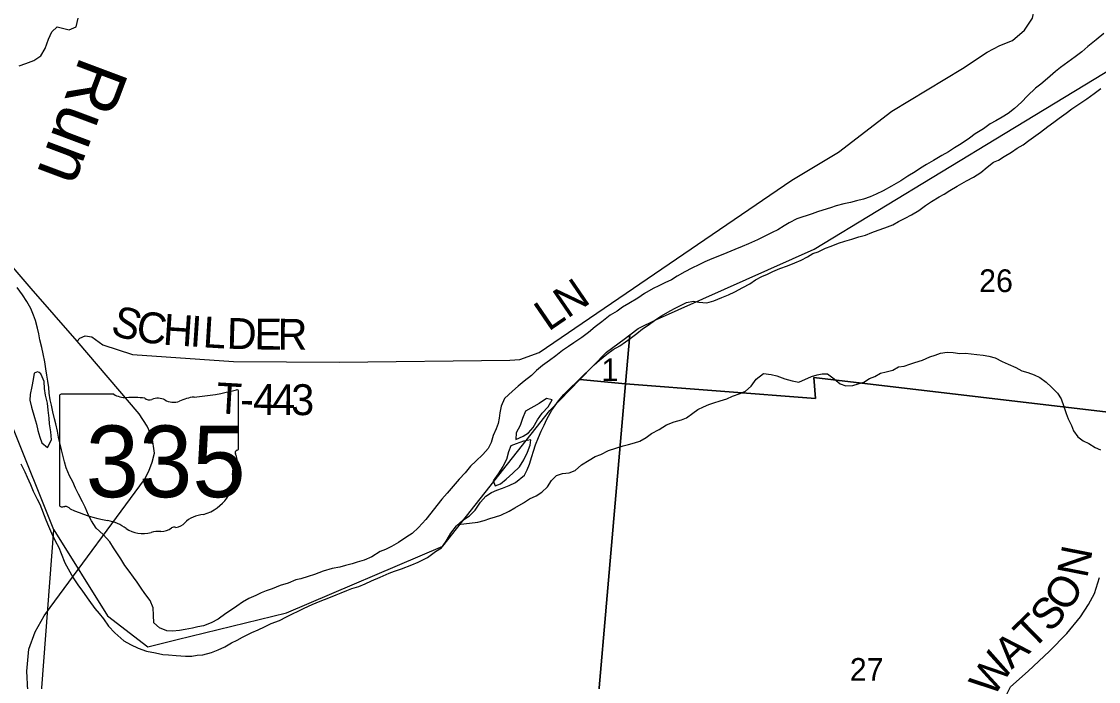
# Model space of a CAD drawing. Extents: x 5.6 to 39.6, y 0.7 to 22.7.
# Drawn here: x 9.058 to 11.039, y 15.732 to 16.946 of the extents above; entities that cross this region are included whole.
import ezdxf

# ---------------------------------------------------------------- set-up
doc = ezdxf.new("R2010")
doc.units = 0
doc.layers.add('Default', color=7, linetype='Continuous')

msp = doc.modelspace()

# ---------------------------------------------------------------- linework, layer by layer
at = {"layer": 'Default'}
for p, q in [((9.4573, 16.161), (9.4573, 16.2657)), ((9.1277, 16.2573), (9.1277, 16.0571)), ((9.2275, 16.2607), (9.1309, 16.2607)), ((9.4572, 16.161), (9.4573, 16.161))]:
    msp.add_line(p, q, dxfattribs=at)
for points in [[(9.1605, 16.3581), (9.1651, 16.3637), (9.1749, 16.3682), (9.1874, 16.3659), (9.2074, 16.3517), (9.2618, 16.3336), (9.4481, 16.3211), (9.6428, 16.3196), (9.956, 16.3235), (9.9746, 16.3245), (10.0103, 16.3372), (10.475, 16.6545), (10.5609, 16.706), (10.6587, 16.7813), (10.7891, 16.8599), (10.8343, 16.8896), (10.8575, 16.9024), (10.8806, 16.9114), (10.9027, 16.9302), (10.9176, 16.9521), (10.9207, 16.9673), (10.9185, 16.9795)], [(9.0533, 16.8646), (9.0659, 16.8691), (9.0807, 16.8746), (9.0933, 16.8828), (9.1014, 16.8964), (9.1077, 16.9137), (9.1139, 16.9273), (9.1235, 16.9363), (9.1356, 16.9335), (9.1458, 16.9311), (9.1587, 16.9367), (9.1623, 16.9526)], [(11.0491, 16.9244), (11.035, 16.9124), (11.0197, 16.9004), (11.0082, 16.8907), (10.996, 16.881), (10.9693, 16.8615), (10.9598, 16.854), (10.9452, 16.8417), (10.933, 16.8312), (10.9231, 16.8237), (10.9086, 16.8098), (10.8971, 16.7978), (10.8848, 16.7862), (10.8726, 16.7772), (10.8616, 16.7705), (10.8501, 16.7637), (10.8399, 16.7578), (10.8273, 16.7488), (10.8124, 16.7395), (10.8017, 16.7316), (10.7865, 16.7215), (10.7743, 16.7141), (10.7632, 16.7066), (10.7506, 16.6999), (10.7354, 16.6906), (10.7224, 16.6831), (10.7114, 16.6764), (10.7015, 16.6697), (10.6885, 16.6619), (10.6756, 16.6533), (10.6584, 16.6436), (10.6432, 16.6346), (10.6302, 16.6287), (10.6188, 16.6239), (10.6067, 16.6195), (10.5938, 16.6162), (10.5827, 16.6136), (10.5706, 16.6111), (10.5562, 16.6071), (10.5459, 16.6038), (10.5318, 16.5994), (10.522, 16.596), (10.5125, 16.5923)], [(10.5036, 16.5132), (10.5136, 16.5192), (10.5235, 16.5225), (10.5368, 16.5292), (10.5471, 16.5332), (10.5608, 16.5384), (10.5726, 16.5421), (10.5855, 16.5458), (10.598, 16.5502), (10.6102, 16.5535), (10.6223, 16.5583), (10.6337, 16.5623), (10.6459, 16.5664), (10.6607, 16.5723), (10.6714, 16.5786), (10.6836, 16.5846), (10.695, 16.5905), (10.7083, 16.5987), (10.7209, 16.6077), (10.732, 16.6152), (10.7457, 16.6238), (10.7552, 16.6286), (10.7655, 16.6353), (10.7789, 16.6435), (10.7964, 16.6532), (10.809, 16.6599), (10.8223, 16.6685), (10.8345, 16.6786), (10.8456, 16.6872), (10.8551, 16.6913), (10.8654, 16.698), (10.8787, 16.7058), (10.8894, 16.7133), (10.9005, 16.7193), (10.9111, 16.7275), (10.9325, 16.7425), (10.9459, 16.7533), (10.9566, 16.7608), (10.9669, 16.7687), (10.9795, 16.7776), (10.9901, 16.7855), (11.0046, 16.7956), (11.0176, 16.8038), (11.0313, 16.8139), (11.0432, 16.8232)], [(10.5125, 16.5923), (10.4843, 16.5835), (10.4702, 16.5757), (10.4607, 16.5702), (10.4489, 16.5631), (10.4386, 16.5579), (10.412, 16.5449), (10.3952, 16.5371), (10.3835, 16.5323), (10.3698, 16.5268), (10.3554, 16.5209), (10.3447, 16.5165), (10.328, 16.5095), (10.3147, 16.5039), (10.304, 16.4984), (10.2907, 16.4924), (10.2782, 16.4858), (10.2637, 16.478), (10.2534, 16.4712), (10.2413, 16.4653), (10.2303, 16.4598), (10.2196, 16.4549), (10.204, 16.446), (10.1914, 16.4374), (10.1751, 16.4274), (10.1636, 16.4207), (10.1533, 16.4136), (10.1408, 16.4058), (10.1251, 16.3938), (10.1133, 16.3845), (10.1007, 16.3744), (10.0885, 16.365), (10.074, 16.3554), (10.0638, 16.3483), (10.0531, 16.3408), (10.0405, 16.3315), (10.0294, 16.3229), (10.0165, 16.3132), (10.0054, 16.3042), (9.9959, 16.2952), (9.9825, 16.2847), (9.9714, 16.2757), (9.9611, 16.2664), (9.9466, 16.2529), (9.94, 16.2389), (9.938, 16.2265), (9.9368, 16.2166), (9.9344, 16.2068), (9.9313, 16.197), (9.9258, 16.1849), (9.9219, 16.172), (9.9161, 16.1611), (9.9065, 16.1498), (9.8936, 16.1375), (9.8836, 16.1281), (9.8737, 16.1161), (9.8629, 16.1041), (9.8522, 16.0917), (9.8411, 16.0789), (9.8311, 16.0673), (9.8216, 16.056), (9.8108, 16.0421), (9.8016, 16.0305), (9.7882, 16.0154), (9.7764, 16.0046), (9.7669, 15.9986), (9.7512, 15.9878), (9.7383, 15.9804), (9.7276, 15.9752), (9.7178, 15.9715), (9.7025, 15.9618), (9.6881, 15.9555), (9.6756, 15.9515), (9.6661, 15.9486), (9.654, 15.9457), (9.6433, 15.9428), (9.6293, 15.9399), (9.6126, 15.9351), (9.5967, 15.9289), (9.5849, 15.9256), (9.572, 15.9212), (9.5625, 15.919), (9.5484, 15.9131), (9.5336, 15.9087), (9.5192, 15.9024), (9.5082, 15.8988), (9.4987, 15.8951), (9.4892, 15.8907), (9.4763, 15.8851), (9.4641, 15.8784), (9.4538, 15.871), (9.4439, 15.8642), (9.434, 15.8571), (9.4199, 15.8467), (9.407, 15.84), (9.3925, 15.8349), (9.3823, 15.8327), (9.3724, 15.8305), (9.3592, 15.828), (9.3486, 15.8263), (9.3357, 15.8249)], [(9.0759, 16.4554), (9.0097, 16.5316)], [(9.328, 15.781), (9.3424, 15.7801), (9.3598, 15.7787), (9.3715, 15.7786), (9.3813, 15.7804), (9.3912, 15.7814), (9.4071, 15.7854), (9.4197, 15.7902), (9.4318, 15.7961), (9.4444, 15.8032), (9.4543, 15.8084), (9.4645, 15.814), (9.4817, 15.8225), (9.4931, 15.8273), (9.5048, 15.8328), (9.517, 15.8388), (9.5326, 15.8443), (9.5451, 15.851), (9.5778, 15.8669), (9.5927, 15.8739), (9.6075, 15.8798), (9.6231, 15.8861), (9.6364, 15.8917), (9.6462, 15.895), (9.6561, 15.8994), (9.6656, 15.9031), (9.6781, 15.9067), (9.6899, 15.9119), (9.7017, 15.9171), (9.7176, 15.9241), (9.734, 15.9315), (9.7439, 15.9352), (9.7568, 15.9396), (9.7758, 15.9466), (9.7875, 15.9518), (9.805, 15.9603), (9.8195, 15.9711), (9.8302, 15.9782), (9.839, 15.9906), (9.8479, 16.0049), (9.8582, 16.0184), (9.8697, 16.0289), (9.8819, 16.0368), (9.8922, 16.0476), (9.9022, 16.0623), (9.9122, 16.0732), (9.9224, 16.0799), (9.9323, 16.0843), (9.9426, 16.088), (9.9551, 16.0928), (9.9665, 16.098), (9.9829, 16.1115), (9.9879, 16.1213), (9.9922, 16.1318), (9.9969, 16.1462), (9.9997, 16.156), (10.0032, 16.1673), (10.009, 16.1809), (10.0141, 16.1926), (10.0191, 16.2039), (10.0241, 16.2149), (10.0334, 16.2311), (10.0457, 16.2484), (10.0553, 16.2604), (10.0671, 16.2716), (10.0793, 16.2833), (10.0919, 16.2956), (10.1019, 16.3058), (10.1114, 16.3144), (10.1214, 16.3234), (10.1343, 16.3342), (10.1465, 16.3428), (10.1583, 16.3499), (10.169, 16.3573), (10.1801, 16.3652), (10.1896, 16.3726), (10.2003, 16.3812), (10.2109, 16.3879), (10.2247, 16.398), (10.2353, 16.4051), (10.2509, 16.414), (10.2605, 16.4192), (10.281, 16.4292), (10.2939, 16.4317), (10.3041, 16.4301), (10.3184, 16.4288), (10.3317, 16.4325), (10.3462, 16.4387), (10.3583, 16.4435), (10.3701, 16.4491), (10.3846, 16.4569), (10.3975, 16.4639), (10.4078, 16.471), (10.4196, 16.4773), (10.4302, 16.4814), (10.4397, 16.4866), (10.453, 16.4921), (10.4667, 16.4969), (10.4807, 16.5021), (10.4918, 16.5072), (10.5036, 16.5132)], [(9.3357, 15.8249), (9.3255, 15.8254), (9.3119, 15.8308), (9.3014, 15.8404), (9.3008, 15.8545), (9.2998, 15.8678), (9.2943, 15.8815), (9.285, 15.8941), (9.2783, 15.9036), (9.2708, 15.9147), (9.2637, 15.9243), (9.2559, 15.9354), (9.2477, 15.9453), (9.2406, 15.9579), (9.2332, 15.9686), (9.2272, 15.9781), (9.2202, 15.9892), (9.2078, 16.0026), (9.1955, 16.0145), (9.1865, 16.0279), (9.181, 16.0382), (9.1747, 16.0527), (9.1703, 16.0626), (9.1629, 16.0767), (9.1569, 16.0881), (9.1525, 16.0992), (9.1462, 16.1106), (9.1399, 16.1251), (9.137, 16.1365), (9.1341, 16.1487), (9.1312, 16.1582), (9.1283, 16.1711), (9.1258, 16.1814), (9.124, 16.1924), (9.1211, 16.2061), (9.1186, 16.2156), (9.1157, 16.2281), (9.1128, 16.2403), (9.1106, 16.2502), (9.1089, 16.2623), (9.1079, 16.2733), (9.1065, 16.2847), (9.1047, 16.2957), (9.1025, 16.3071), (9.1008, 16.3204), (9.0979, 16.3348), (9.095, 16.3466), (9.0918, 16.3607), (9.0896, 16.3717), (9.0871, 16.382), (9.0835, 16.3964), (9.0801, 16.4059), (9.075, 16.4185), (9.0676, 16.4311), (9.0597, 16.4433), (9.0501, 16.4567)], [(9.071, 15.7062), (9.0694, 15.7157), (9.0678, 15.751), (9.0715, 15.7916), (9.0832, 15.8235), (9.0994, 15.8528), (9.1107, 15.8684), (9.2839, 16.1036), (9.2922, 16.1192), (9.2982, 16.1355), (9.3024, 16.1522), (9.2985, 16.1818), (9.2893, 16.2016), (9.2741, 16.2247), (9.1605, 16.3581), (9.0759, 16.4554)], [(8.2518, 15.7856), (8.2639, 15.7623), (8.2659, 15.4721), (9.0725, 15.4217), (9.1174, 16.0112), (9.0418, 16.1995), (9.0049, 16.4106), (8.3039, 16.4383), (8.2518, 16.391)], [(10.5109, 16.2932), (10.5212, 16.2964), (10.5308, 16.2984), (10.5406, 16.2982), (10.5525, 16.2892), (10.5637, 16.2795), (10.5742, 16.2759), (10.5871, 16.2767), (10.597, 16.2799), (10.6073, 16.2827), (10.618, 16.2893), (10.6276, 16.2932), (10.6383, 16.2991), (10.6486, 16.3019), (10.6604, 16.305), (10.6712, 16.3109), (10.6814, 16.3122), (10.6917, 16.3157), (10.7013, 16.3189), (10.7154, 16.3232), (10.7288, 16.3293), (10.7387, 16.3325), (10.7482, 16.3361), (10.7604, 16.3377), (10.7717, 16.3371), (10.7842, 16.3353), (10.7941, 16.3362), (10.8152, 16.3335), (10.8269, 16.3324), (10.8375, 16.3307), (10.8492, 16.3274), (10.8619, 16.321), (10.8731, 16.3162), (10.887, 16.3095), (10.8982, 16.3035), (10.9092, 16.3006), (10.9208, 16.2962), (10.9313, 16.2914), (10.9425, 16.2828), (10.9525, 16.2739), (10.9636, 16.2623), (10.9702, 16.2519), (10.9755, 16.2381), (10.9798, 16.2251), (10.9834, 16.2152), (10.9892, 16.2033), (10.9931, 16.193), (11.0008, 16.1822), (11.0109, 16.1747), (11.021, 16.17), (11.0329, 16.1629), (11.0427, 16.1585)], [(9.081, 16.2996), (9.0793, 16.2879), (9.0769, 16.2746), (9.0741, 16.2602), (9.0732, 16.25), (9.0761, 16.2367), (9.0819, 16.2176), (9.0852, 16.2058), (9.0881, 16.194), (9.0914, 16.1815), (9.0954, 16.1712), (9.1056, 16.1627), (9.1133, 16.177), (9.1116, 16.1915), (9.1095, 16.2063), (9.1085, 16.2169), (9.1071, 16.2314), (9.1054, 16.2439), (9.1021, 16.2591), (9.1004, 16.2713), (9.0994, 16.2842)], [(9.0994, 16.2842), (9.0957, 16.2928), (9.0935, 16.298), (9.0905, 16.3006), (9.087, 16.302), (9.081, 16.2996)], [(9.8609, 16.0209), (9.8972, 16.0253), (9.909, 16.0282), (9.9196, 16.0319), (9.9295, 16.0348), (9.9394, 16.0381), (9.955, 16.0455), (9.9653, 16.0514), (9.981, 16.0611), (9.9924, 16.0682), (10.0046, 16.0738), (10.0153, 16.0805), (10.0256, 16.0902), (10.0326, 16.1019), (10.0422, 16.1113), (10.0532, 16.1149), (10.065, 16.1159), (10.0764, 16.1204), (10.0879, 16.1309), (10.102, 16.1394), (10.1131, 16.1458), (10.1233, 16.1498), (10.1374, 16.1569), (10.1511, 16.1616), (10.1648, 16.1656), (10.1743, 16.1682), (10.1857, 16.1711), (10.1952, 16.1744), (10.2071, 16.1811), (10.217, 16.1882), (10.2307, 16.196), (10.2441, 16.2042), (10.2585, 16.2101), (10.2718, 16.2134), (10.2814, 16.2171), (10.2925, 16.226), (10.302, 16.2328), (10.3123, 16.2376), (10.3222, 16.242), (10.3317, 16.2446), (10.3431, 16.2486), (10.3553, 16.2523), (10.366, 16.2571), (10.3796, 16.2618), (10.3899, 16.2663), (10.3999, 16.2756), (10.4095, 16.2881), (10.4229, 16.2989), (10.4369, 16.2972), (10.4475, 16.2945), (10.4622, 16.289), (10.4754, 16.285), (10.4875, 16.283), (10.5109, 16.2932)], [(9.9852, 16.2296), (9.9793, 16.216), (9.975, 16.2028), (9.9676, 16.1896), (9.9675, 16.1774), (9.9808, 16.1833), (9.9904, 16.1897), (9.9992, 16.1994), (10.0073, 16.2138), (10.0154, 16.2258), (10.0269, 16.2374), (10.0339, 16.2503), (10.0237, 16.253), (10.0103, 16.2437)], [(10.0103, 16.2437), (9.9852, 16.2296)], [(9.9583, 16.1654), (9.9536, 16.1544), (9.95, 16.1408), (9.9431, 16.1276), (9.9346, 16.1144), (9.9257, 16.1016), (9.9294, 16.0921), (9.9389, 16.0958), (9.9492, 16.1044), (9.9615, 16.1156), (9.9738, 16.1272), (9.9822, 16.1397), (9.9885, 16.154), (9.9935, 16.1669), (9.9948, 16.1767), (9.9811, 16.1742), (9.9678, 16.1691)], [(9.9678, 16.1691), (9.9583, 16.1654)], [(9.0564, 16.1329), (9.0638, 16.118), (9.0686, 16.1081), (9.0745, 16.0947), (9.0793, 16.0825), (9.0864, 16.0677), (9.0916, 16.0581), (9.1026, 16.0296), (9.1078, 16.0182), (9.1133, 16.0048), (9.12, 15.9907), (9.1263, 15.9789), (9.1311, 15.9675), (9.1377, 15.9503), (9.144, 15.9393), (9.1529, 15.9229), (9.1618, 15.9103), (9.17, 15.8984), (9.182, 15.882), (9.1928, 15.8667), (9.201, 15.8571), (9.2088, 15.8472), (9.2181, 15.8338), (9.2293, 15.8215), (9.2462, 15.8069), (9.2586, 15.8), (9.2722, 15.7938), (9.288, 15.7883), (9.3042, 15.7847), (9.3178, 15.7819), (9.328, 15.781)], [(10.7121, 15.5385), (10.7289, 15.5406), (10.7424, 15.5448), (10.764, 15.5548), (10.7815, 15.5703), (10.8123, 15.5978), (10.8409, 15.6257), (10.8554, 15.6454), (10.862, 15.6628), (10.8647, 15.6856), (10.8702, 15.7091), (10.8771, 15.7227), (10.9094, 15.751), (10.9487, 15.7883), (10.9807, 15.8204), (11.0062, 15.8514), (11.0204, 15.874), (11.0319, 15.8941), (11.0411, 15.9233)]]:
    msp.add_lwpolyline(points, dxfattribs=at)
for points in [[(11.1778, 16.9289), (11.1299, 16.2192), (10.5154, 16.2914), (10.5184, 16.2529), (10.169, 16.28), (10.1768, 16.3696), (10.1925, 16.3816), (10.2261, 16.3983), (10.5161, 16.5272), (10.8674, 16.7406)], [(10.0851, 16.2878), (10.1338, 16.3378), (10.1664, 16.3617), (10.1768, 16.3696), (10.169, 16.28)], [(10.0851, 16.2878), (10.169, 16.28), (10.0852, 15.3096), (9.1119, 15.4192), (9.0725, 15.4217), (9.1174, 16.0112), (9.2162, 15.8528), (9.2902, 15.796), (9.3445, 15.8093), (9.5455, 15.8584), (9.8328, 15.9813), (10.0295, 16.2307)], [(10.169, 16.28), (10.5184, 16.2529), (10.5154, 16.2914), (11.1299, 16.2192), (11.0648, 15.2501), (10.8842, 15.2625), (10.0852, 15.3096)]]:
    msp.add_lwpolyline(points, close=True, dxfattribs=at)
for centre, major_axis, start_param, end_param in [((9.3399, 16.5335), (0.3495, 0), 4.814394, 5.042369), ((9.4536, 16.2661), (0.00367, 0), 6.141152, 7.989035), ((9.1315, 16.2577), (0.00382, 0), 1.712693, 3.28349), ((9.2504, 16.2839), (0.037, 0), 4.042523, 4.731795), ((9.2627, 16.1483), (0.133, 0), 1.404758, 1.657858), ((9.2929, 16.2587), (0.0107, 0), 3.836095, 5.185415), ((9.3086, 16.2356), (0.0222, 0), 0.950623, 2.079405), ((9.3373, 16.2673), (0.0267, 0), 4.081561, 5.145723), ((9.3845, 16.1996), (0.0703, 0), 1.699011, 2.107814), ((9.4564, 16.1533), (0.00568, 0), 1.883978, 3.671073), ((9.4203, 16.1401), (0.0341, 0), 5.934695, 6.695948), ((9.4534, 16.1606), (0.00393, 0), 5.05454, 6.418171), ((9.4704, 16.1172), (0.0248, 0), 2.387724, 3.262537), ((9.3595, 16.1038), (0.0874, 0), 5.101752, 6.440018), ((9.1315, 16.0567), (0.00385, 0), 3.00124, 4.508301), ((9.1321, 16.0772), (0.0294, 0), 4.665946, 4.897461), ((9.1381, 16.0456), (0.0106, 0), 0.519207, 1.627899), ((9.2719, 16.2254), (0.2524, 0), 4.195997, 4.488961), ((9.1967, 15.9672), (0.079, 0), 0.823519, 1.323587), ((9.3963, 16.0009), (0.0479, 0), 1.647645, 2.488434), ((9.2821, 16.0446), (0.0501, 0), 4.026481, 4.996735), ((9.311, 15.9754), (0.0412, 0), 1.495662, 1.94098), ((9.3147, 16.0296), (0.0267, 0), 4.691044, 5.507374), ((9.3389, 16.0102), (0.00752, 0), 1.147584, 2.315152), ((9.3357, 16.0377), (0.0282, 0), 4.937069, 5.64225)]:
    msp.add_ellipse(centre, major_axis=major_axis, ratio=0.8, start_param=start_param, end_param=end_param, dxfattribs=at)

# ---------------------------------------------------------------- texts
for s, height, rotation, p in [('Run', 0.09471, 249.4048, (9.167, 16.885)), ('26', 0.04182, 0, (10.8194, 16.4485)), ('LN', 0.05682, 34.4017, (10.0272, 16.3752)), ('S', 0.0568, 342.5658, (9.2195, 16.3718)), ('C', 0.0568, 353.1268, (9.2673, 16.3579)), ('H', 0.0568, 356.1924, (9.3169, 16.352)), ('I', 0.0568, 356.1724, (9.3668, 16.3487)), ('L', 0.0568, 356.5694, (9.3905, 16.3471)), ('D', 0.0568, 358.311, (9.4348, 16.3445)), ('E', 0.0568, 359.5835, (9.4862, 16.343)), ('R', 0.0568, 359.6453, (9.5287, 16.3426)), ('1', 0.0418, 0, (10.1247, 16.2847)), ('T', 0.0568, 356.6942, (9.4149, 16.2258)), ('4', 0.0568, 359.4049, (9.4836, 16.2229)), ('4', 0.0568, 359.614, (9.5188, 16.2225)), ('3', 0.0568, 359.6675, (9.5539, 16.2223)), ('-', 0.0568, 358.9564, (9.4598, 16.2233)), ('N', 0.0568, 78.9071, (11.0181, 15.921)), ('O', 0.0568, 57.4972, (10.9826, 15.8574)), ('S', 0.0568, 47.1978, (10.9498, 15.8205)), ('T', 0.0568, 44.3834, (10.9173, 15.7886)), ('A', 0.0568, 42.6192, (10.8791, 15.7534)), ('W', 0.0568, 56.6813, (10.8453, 15.7012)), ('27', 0.04182, 0, (10.5815, 15.7335))]:
    msp.add_text(s, height=height, rotation=rotation, dxfattribs=at).set_placement(p)
msp.add_text('335', height=0.13184, dxfattribs=at).set_placement((9.176, 16.0712))

doc.saveas('drawing.dxf')
